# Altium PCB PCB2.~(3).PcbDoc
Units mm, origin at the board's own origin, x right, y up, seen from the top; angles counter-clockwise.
Board outline 50 x 50 mm, 2 copper layers (Top Layer, Bottom Layer); 14 components, 16 nets, 44 pads, 7 vias.
Unrouted connection lines stored in the file: 22.
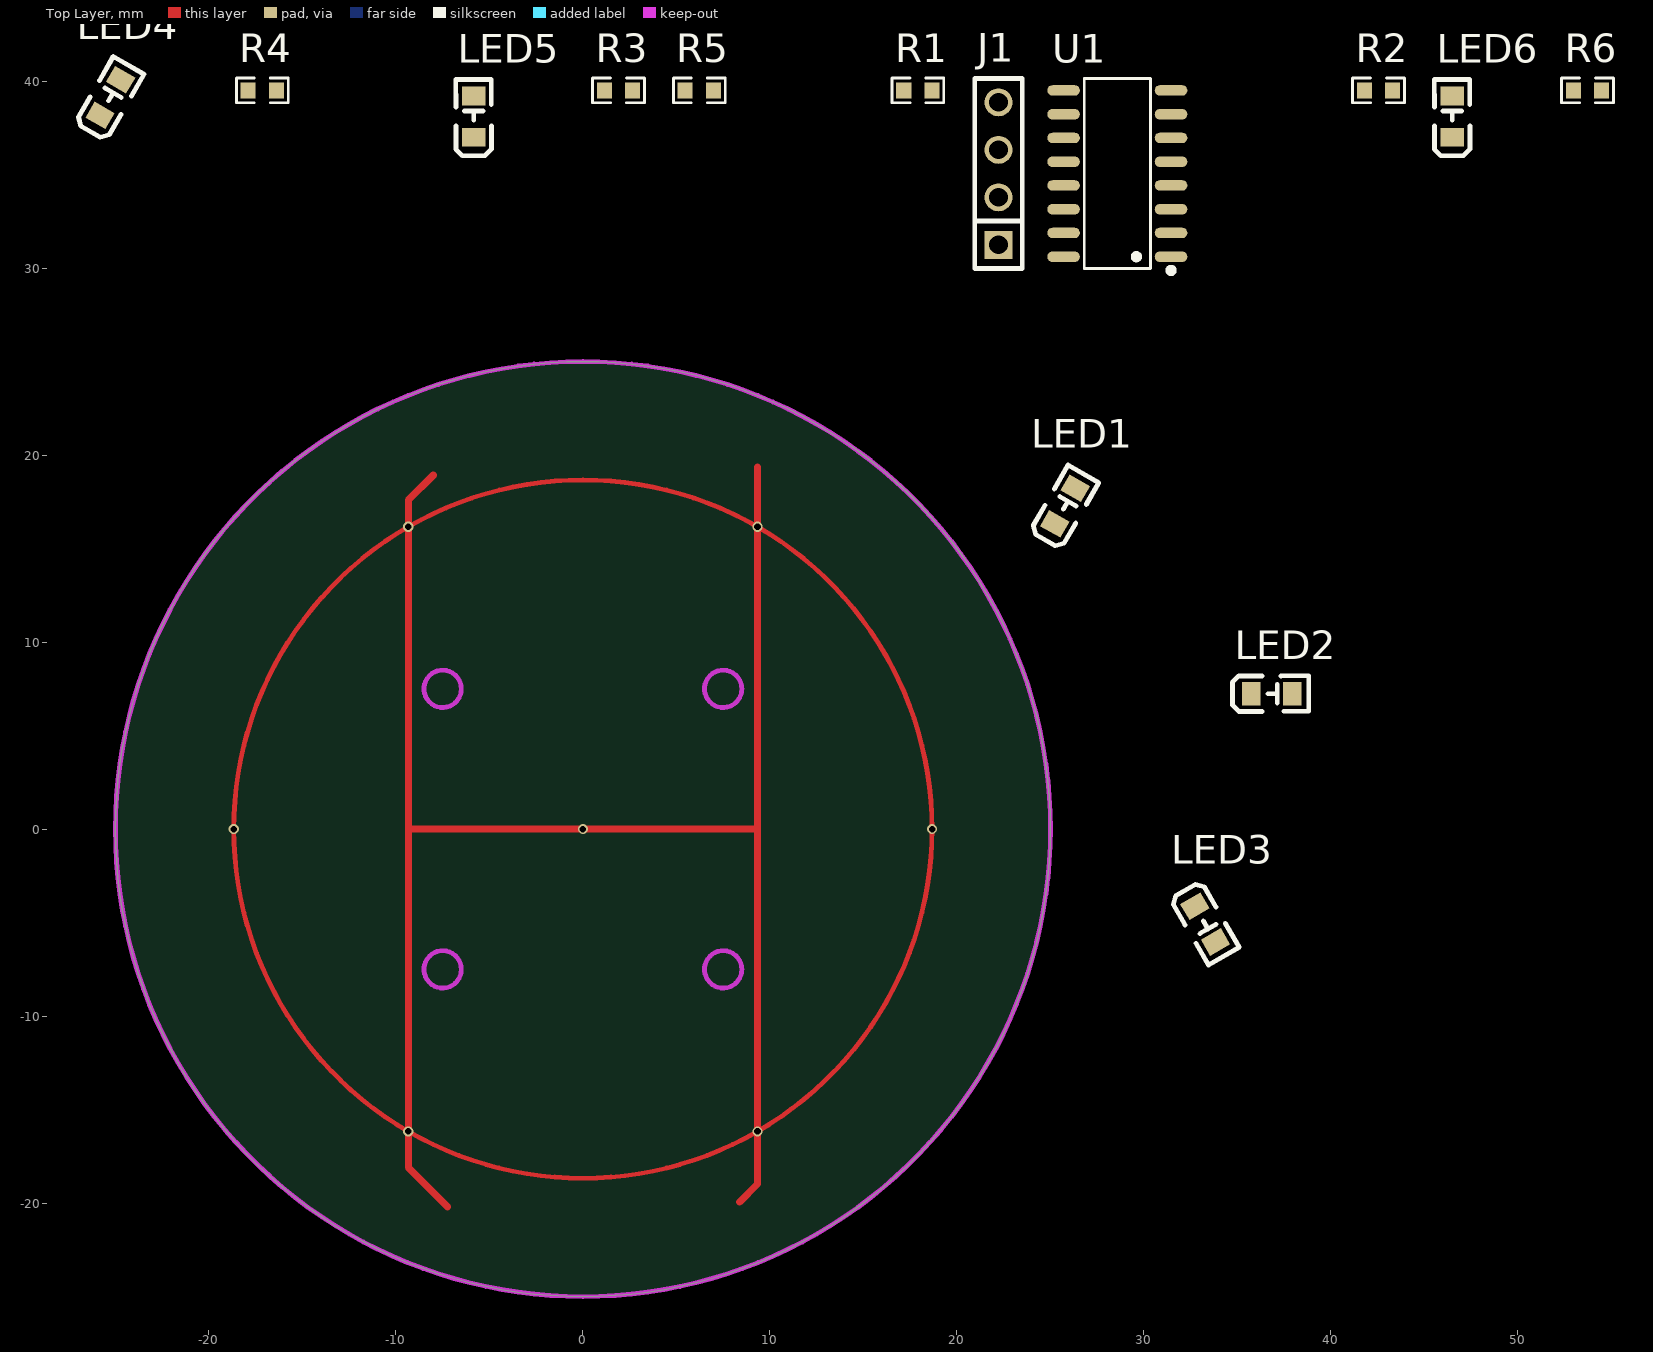
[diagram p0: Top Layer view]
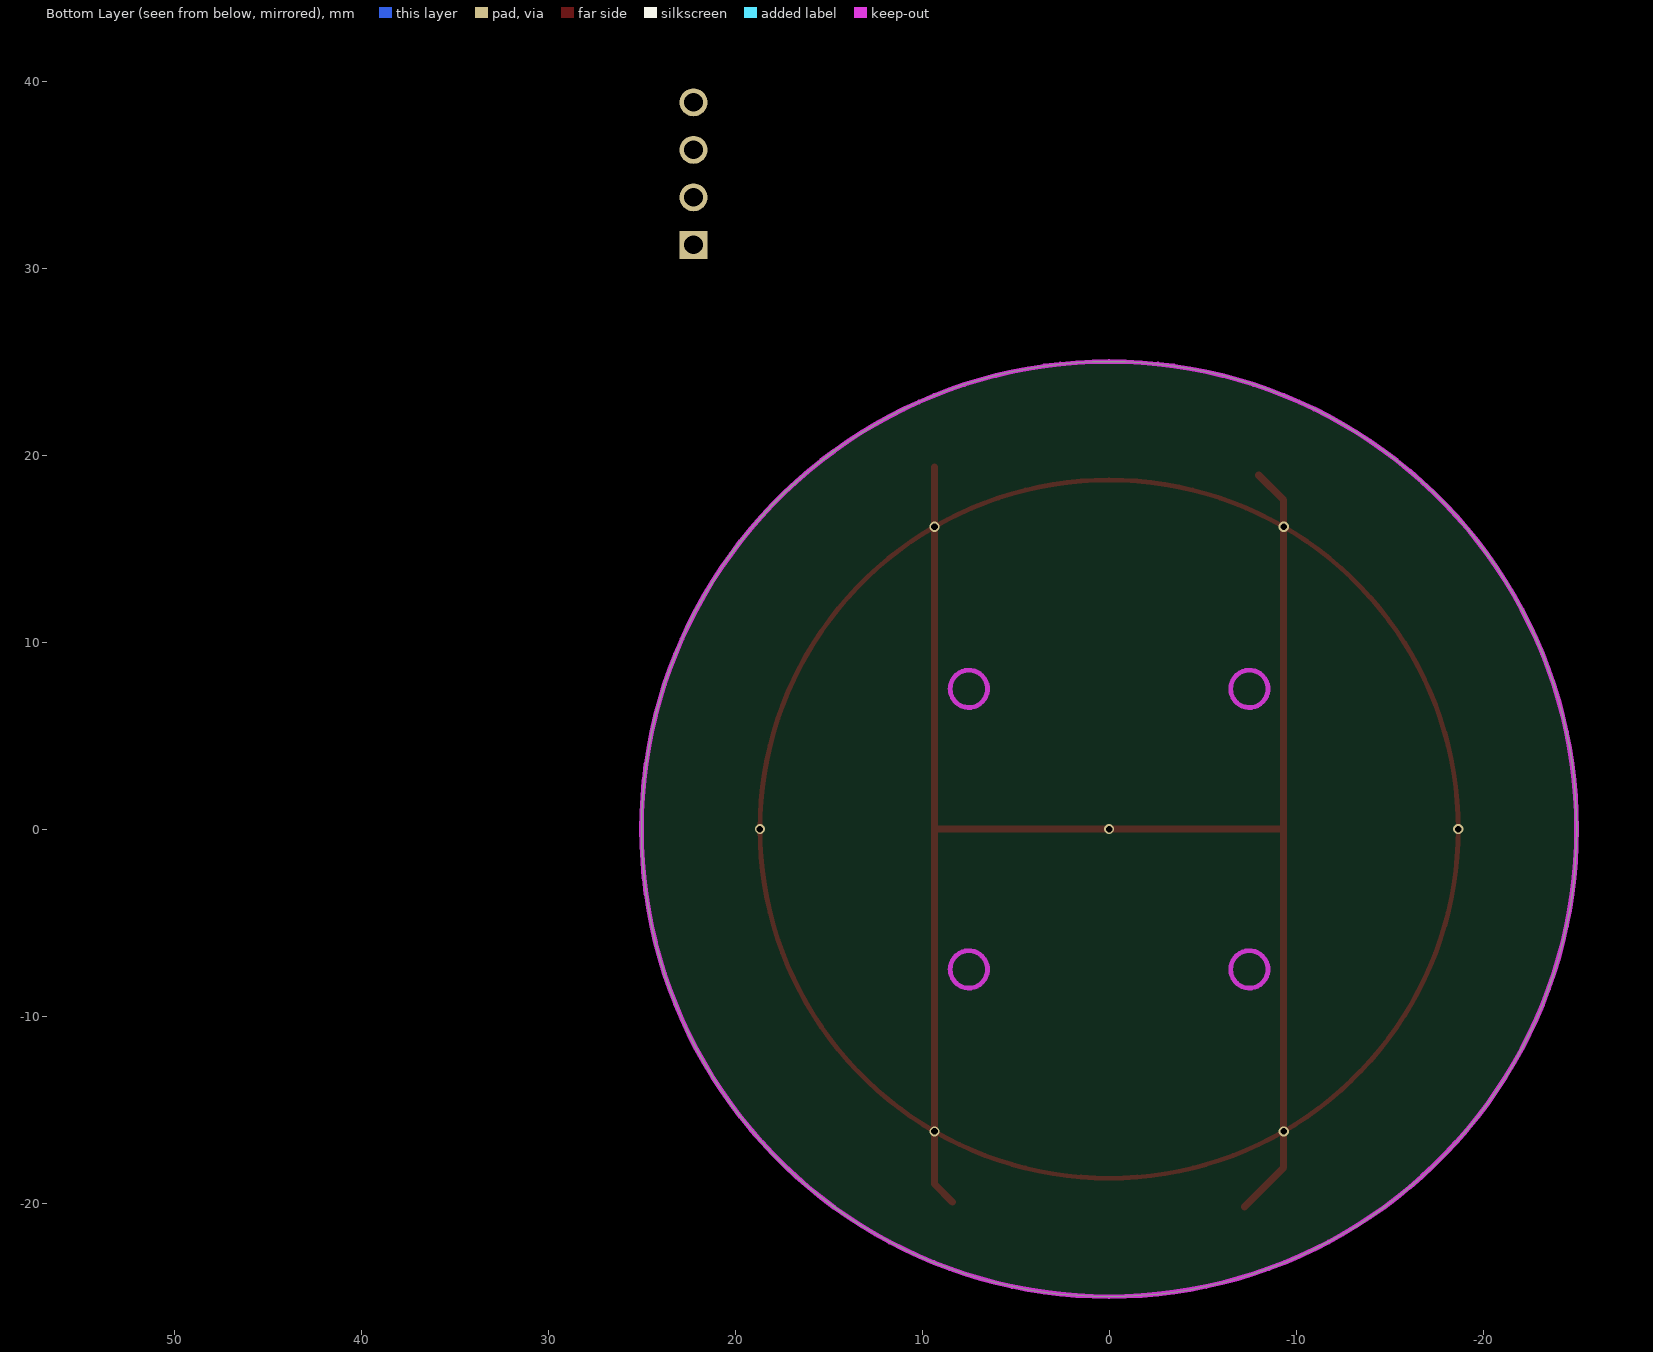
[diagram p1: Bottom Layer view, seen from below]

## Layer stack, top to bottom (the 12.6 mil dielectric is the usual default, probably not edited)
Top Solder: solder mask 0.0102, Solder Resist, Dk 3.5
Top Layer: signal copper 0.0356
Dielectric 1: dielectric 0.32, FR-4, Dk 4.8
Bottom Layer: signal copper 0.0356
Bottom Solder: solder mask 0.0102, Solder Resist, Dk 3.5

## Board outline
-25,0 ccw(c0,0) 0,-25 ccw(c0,0) 25,0 ccw(c0,0) 0,25 ccw(c0,0)

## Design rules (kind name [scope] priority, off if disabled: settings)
Clearance [All] p1: gap=0.254 ignorepadtopadclearanceinfootprint=FALSE except(0: Arc-Hole Track-Hole SMDPad-Hole THPad-Hole Via-Hole Fill-Hole Poly-Hole Region-Hole Text-Hole)
PlaneConnect [All] p1: planeconnectstyle=Direct reliefexpansion=0.508 reliefentries=4 reliefconductorwidth=0.254 reliefairgap=0.254
PolygonConnect [All] p1: connectstyle=Direct reliefconductorwidth=0.254 reliefentries=4 polygonreliefangle="90 Angle" airgapwidth=0.254
RoutingVias [All] p1: holewidth=0.711 width=1.27 viastyle="Through Hole" minholewidth=0.025 minwidth=0.025 maxholewidth=0.711 maxwidth=1.27
SolderMaskExpansion [All] p1: expansion=0.102 istentingtop=FALSE
Width [All] p1: maxlimit=2.54 minlimit=0.025 preferedwidth=0.254
29 further rules are at their usual default settings.

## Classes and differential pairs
component class Sheet1: J1 LED1 LED2 LED4 LED5 R1 R2 R3 R4 R5 U1

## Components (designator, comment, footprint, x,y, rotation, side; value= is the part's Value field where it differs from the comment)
J1 "CON4" SIP4 22.225,31.242 r90 top
LED1 "XL-2012SURC" LED0805-RD_RED 25.781,17.272 r60 top
LED2 "XL-2012SURC" LED0805-RD_RED 36.83,7.239 r0 top
LED3 "XL-2012SURC" LED0805-RD_RED 33.274,-5.08 r300 top
LED4 "XL-2012SURC" LED0805-RD_RED -25.273,39.116 r60 top
LED5 "XL-2012SURC" LED0805-RD_RED -5.842,38.1 r90 top
LED6 "XL-2012SURC" LED0805-RD_RED 46.482,38.1 r90 top
R1 "220Ω" R0603 17.907,39.497 r0 top
R2 "220Ω" R0603 42.545,39.497 r0 top
R3 "220Ω" R0603 1.905,39.497 r0 top
R4 "220Ω" R0603 -17.145,39.497 r0 top
R5 "220Ω" R0603 6.223,39.497 r0 top
R6 "220Ω" R0603 53.721,39.497 r0 top
U1 "HEF4017BT,653" SOP-16_L10.0-W3.9-P1.27-LS6.0-BL 28.575,35.052 r90 top

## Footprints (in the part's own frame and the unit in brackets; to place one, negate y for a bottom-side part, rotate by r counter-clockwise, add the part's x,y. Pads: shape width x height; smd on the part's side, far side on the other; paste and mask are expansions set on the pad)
LED0805-RD_RED [mm]
  rect 1x1.25 smd: 1(-1.1,0) 2(1.1,0)
  silkscreen extent -2.1,-0.95 1.98,0.96
R0603 [mm]
  rect 0.806x0.864 smd: 1(-0.753,0) 2(0.753,0)
  silkscreen extent -1.39,-0.66 1.39,0.66
SIP4 [mm]
  rect 1.5x1.5 hole 1: 1(0,0)
  round 1.5 hole 1: 2(2.54,0) 3(5.08,0) 4(7.62,0)
  silkscreen extent -1.27,-1.27 8.89,1.27
SOP-16_L10.0-W3.9-P1.27-LS6.0-BL [mm]
  oval 0.56x1.745 smd: 1(-4.445,-2.872) 2(-3.175,-2.872) 3(-1.905,-2.872) 4(-0.635,-2.872) 5(0.635,-2.872) 6(1.905,-2.872) 7(3.175,-2.872) 8(4.445,-2.872) 9(4.445,2.872) 10(3.175,2.872) 11(1.905,2.872) 12(0.635,2.872) 13(-0.635,2.872) 14(-1.905,2.872) 15(-3.175,2.872) 16(-4.445,2.872)
  silkscreen extent -5.33,-3.02 5.08,1.77

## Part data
J1: "Connector"
LED1 LED2 LED3 LED4 LED5 LED6: Color Temperature=-, Emitted Color=红色, Forward Current=25mA, JLCPCB Part Class=扩展库, Lens Color=无色透明透镜, Manufacturer=XINGLIGHT(成兴光), Operating Temperature=-30℃~+85℃, Power Dissipation=55mW
R1 R2 R3 R4 R5 R6: library part 0603WAF2200T5E, JLCPCB Part Class=基础库, LCSC Part Name="220Ω ±1% 100mW 厚膜电阻", Manufacturer=UNI-ROYAL(厚声), Operating Temperature Range=-55℃~+155℃, Overload Voltage (Max)=75V, Power(Watts)=100mW, Temperature Coefficient=±100ppm/℃, Tolerance=±1%
U1: JLCPCB Part Class=扩展库, LCSC Part Name="30MHz 10位十进制计数器", Manufacturer=Nexperia(安世), Operating Temperature=-40℃~+85℃, Voltage - Supply=4.5V~15.5V

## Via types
v1: diameter 0.55, hole 0.35, Top Layer to Bottom Layer, 7 vias

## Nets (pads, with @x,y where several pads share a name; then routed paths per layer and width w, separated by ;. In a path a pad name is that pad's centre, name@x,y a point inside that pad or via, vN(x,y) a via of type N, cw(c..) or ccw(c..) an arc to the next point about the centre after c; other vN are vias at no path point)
+5V: J1.1 U1.16
CLK: J1.4 U1.14
GND: J1.2 LED1.1 LED2.1 LED3.1 LED4.1 LED5.1 LED6.1 U1.8
NetLED1_2: LED1.2 R1.1
NetLED2_2: LED2.2 R2.1
NetLED3_2: LED3.2 R3.1
NetLED4_2: LED4.2 R4.1
NetLED5_2: LED5.2 R5.2
NetLED6_2: LED6.2 R6.1
NetR1_2: R1.2 U1.3
NetR2_2: R2.2 U1.2
NetR3_2: R3.2 U1.4
NetR4_2: R4.2 U1.7
NetR5_1: R5.1 U1.10
NetR6_2: R6.2 U1.1
RST: J1.3 U1.15
pads on no net: U1.5 U1.6 U1.9 U1.11 U1.12 U1.13
copper on no net: | length 216.2
  Top Layer w0.254: v1(18.67,0) ccw(c0,0) v1(18.67,0)
  Top Layer w0.381: -8.001,18.923 -9.335,17.589 -9.335,0 ; -7.239,-20.193 -9.335,-18.097 -9.335,0 ; 8.382,-19.939 9.335,-18.986 9.335,0 ; 9.335,19.367 9.335,0 ; -9.335,0 v1(0,0) 9.335,0
  other v1: -9.335,-16.169 9.335,-16.169 -18.67,0 -9.335,16.169 9.335,16.169

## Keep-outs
Keep-Out Layer:
  circle w0.254: c-7.5,-7.5 r1
  circle w0.254: c7.5,-7.5 r1
  circle w0.254: c-7.5,7.5 r1
  circle w0.254: c7.5,7.5 r1
  circle w0.254: c0,0 r25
